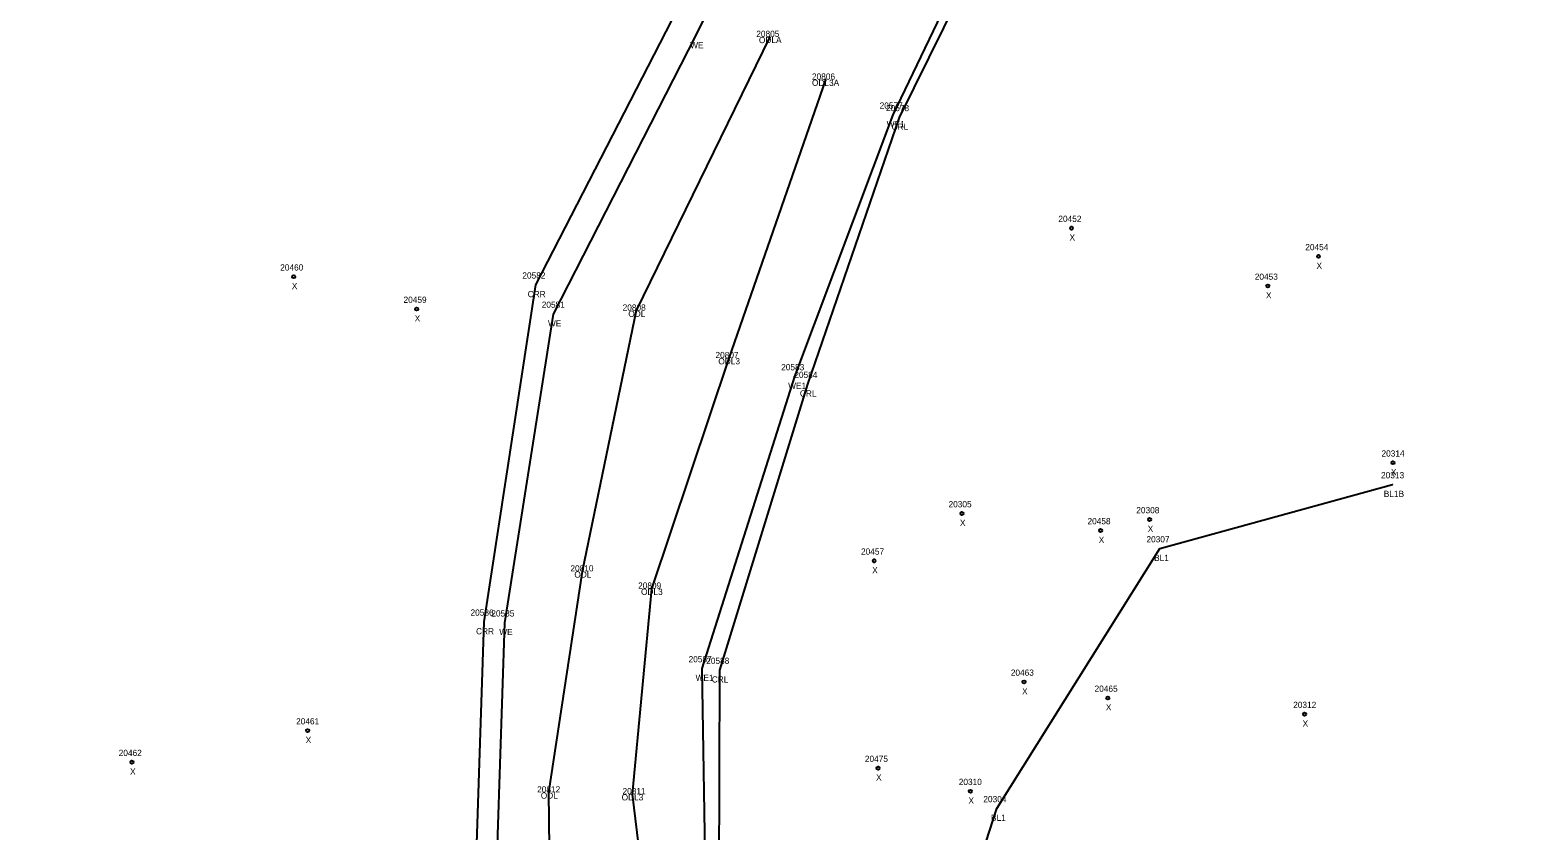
# Model space of a CAD drawing. Extents: x 1965722 to 1969964, y 1117078 to 1118461.
# Drawn here: x 1967718.8 to 1967961.6, y 1117958.8 to 1118087.7 of the extents above; entities that cross this region are included whole.
import ezdxf

# ---------------------------------------------------------------- set-up
doc = ezdxf.new("R2010")
doc.units = 0
for name, color, linetype in [('RD_DTM_BkLn1', 7, 'Continuous'), ('RD_EX_H2O', 7, 'Continuous'), ('RD_EX_H2O_txCode', 7, 'Continuous'), ('RD_SMD_Locator', 7, 'Continuous'), ('RD_SMD_Misc', 7, 'Continuous')]:
    doc.layers.add(name, color=color, linetype=linetype)

msp = doc.modelspace()

# ---------------------------------------------------------------- linework, layer by layer
at = {"layer": 'RD_DTM_BkLn1'}
msp.add_lwpolyline([(1967864.65, 1117932.01), (1967874.44, 1117962.38), (1967900.7, 1118004.22), (1967938.17, 1118014.53)], dxfattribs=at)
at = {"layer": 'RD_EX_H2O'}
for points in [[(1967852.4, 1118390.04), (1967912.21, 1118383.64), (1967925.08, 1118336.82), (1967944.14, 1118294.4), (1967946.67, 1118243.15), (1967961.58, 1118191.28), (1967922.84, 1118148.62), (1967880.18, 1118117.11), (1967858.72, 1118073.64), (1967843.96, 1118030.69), (1967829.77, 1117984.65), (1967829.63, 1117934.73), (1967834.65, 1117903.36)], [(1967848.54, 1118347.45), (1967880.38, 1118337.78), (1967886.93, 1118331.58), (1967896.4, 1118282.85), (1967906.33, 1118232.39), (1967914.38, 1118193.81), (1967904.29, 1118181.59), (1967847.52, 1118139.25), (1967823.99, 1118093.05), (1967800.15, 1118046.69), (1967791.83, 1117992.41), (1967789.93, 1117935.61), (1967798.32, 1117889.19), (1967796.67, 1117880.97)], [(1967849.83, 1118135.18), (1967825.91, 1118086.77), (1967802.99, 1118041.98), (1967795.15, 1117992.28), (1967793.27, 1117935.35), (1967800.64, 1117889.8), (1967800.4, 1117872.52), (1967800.8, 1117854.99), (1967811.67, 1117837.73), (1967837.15, 1117809.04), (1967808.01, 1117752.12), (1967788.48, 1117706.78), (1967783.36, 1117689.17), (1967764.63, 1117648.93), (1967738.42, 1117613.44), (1967731.11, 1117607.31), (1967718.77, 1117573.47), (1967736.01, 1117517.29), (1967781.71, 1117484.69), (1967799.34, 1117478.73), (1967814.43, 1117469.18)], [(1967879.07, 1118118.61), (1967857.7, 1118074.04), (1967841.84, 1118031.93), (1967826.93, 1117984.9), (1967827.73, 1117935.27), (1967832.39, 1117902.59), (1967835.81, 1117893.8), (1967842.37, 1117871.73), (1967853.33, 1117857.05), (1967865.72, 1117824.99), (1967870.38, 1117810.73), (1967864.06, 1117791.33), (1967853.89, 1117756.14), (1967832.83, 1117722.61), (1967813.26, 1117679.41), (1967797.31, 1117630.26), (1967771.82, 1117595.7), (1967769.03, 1117583.97), (1967753.91, 1117565.22), (1967760.74, 1117542.39), (1967793.79, 1117511.28), (1967804.07, 1117502.92), (1967828.12, 1117499.18)], [(1967837.87, 1118086.59), (1967816.35, 1118042.52), (1967807.65, 1118000.54), (1967802.25, 1117964.95), (1967802.7, 1117929.05), (1967808.24, 1117891.66), (1967818.1, 1117847.27), (1967841.92, 1117812.91), (1967830.83, 1117773.47), (1967807.55, 1117730.13), (1967792.1, 1117688.21), (1967759.2, 1117626.42), (1967746.8, 1117597.58), (1967728.31, 1117575.82), (1967748.97, 1117519.79), (1967787.59, 1117491.86), (1967802.7, 1117484.72), (1967813.63, 1117479.24)], [(1967846.86, 1118079.71), (1967831.29, 1118034.88), (1967818.84, 1117997.76), (1967815.72, 1117964.67), (1967820.18, 1117928.06), (1967829.19, 1117896.79), (1967834.11, 1117854.1), (1967863.47, 1117815.02), (1967842.32, 1117765.95), (1967826.02, 1117725.1), (1967807.77, 1117682.35), (1967775.42, 1117611.81), (1967754.74, 1117587.12), (1967745.94, 1117565.65), (1967761.23, 1117525.28), (1967787.1, 1117502.15), (1967805.18, 1117494.11), (1967821.41, 1117490.36)]]:
    msp.add_lwpolyline(points, dxfattribs=at)
at = {"layer": 'RD_SMD_Locator'}
for centre, radius in [((1967825.91, 1118086.77), 0.001), ((1967837.87, 1118086.59), 0.001), ((1967846.86, 1118079.71), 0.001), ((1967857.7, 1118074.04), 0.001), ((1967858.72, 1118073.64), 0.001), ((1967886.47, 1118055.81), 0.25), ((1967926.25, 1118051.25), 0.25), ((1967761.22, 1118047.98), 0.25), ((1967800.15, 1118046.69), 0.001), ((1967918.1, 1118046.49), 0.25), ((1967781.01, 1118042.78), 0.25), ((1967802.99, 1118041.98), 0.001), ((1967816.35, 1118042.52), 0.001), ((1967831.29, 1118034.88), 0.001), ((1967841.84, 1118031.93), 0.001), ((1967843.96, 1118030.69), 0.001), ((1967938.24, 1118018.03), 0.25), ((1967938.17, 1118014.53), 0.001), ((1967868.83, 1118009.86), 0.25), ((1967899.06, 1118008.9), 0.25), ((1967891.17, 1118007.13), 0.25), ((1967900.7, 1118004.22), 0.001), ((1967807.65, 1118000.54), 0.001), ((1967854.7, 1118002.24), 0.25), ((1967818.84, 1117997.76), 0.001), ((1967791.83, 1117992.41), 0.001), ((1967795.15, 1117992.28), 0.001), ((1967826.93, 1117984.9), 0.001), ((1967829.77, 1117984.65), 0.001), ((1967878.84, 1117982.74), 0.25), ((1967892.33, 1117980.16), 0.25), ((1967924.02, 1117977.55), 0.25), ((1967763.46, 1117974.91), 0.25), ((1967735.17, 1117969.82), 0.25), ((1967855.32, 1117968.87), 0.25), ((1967802.25, 1117964.95), 0.001), ((1967815.72, 1117964.67), 0.001), ((1967870.19, 1117965.15), 0.25), ((1967874.44, 1117962.38), 0.001)]:
    msp.add_circle(centre, radius, dxfattribs=at)

# ---------------------------------------------------------------- texts
at = {"layer": 'RD_EX_H2O_txCode'}
for s, p in [('WE', (1967825.07, 1118084.77)), ('20805', (1967835.71, 1118086.59)), ('ODLA', (1967836.14, 1118085.59)), ('20806', (1967844.68, 1118079.71)), ('ODL3A', (1967844.68, 1118078.71)), ('20577', (1967855.58, 1118075.04)), ('20578', (1967856.6, 1118074.64)), ('WE1', (1967856.72, 1118072.04)), ('CRL', (1967857.49, 1118071.64)), ('20582', (1967798.04, 1118047.69)), ('CRR', (1967798.9, 1118044.69)), ('20581', (1967801.16, 1118042.98)), ('20808', (1967814.19, 1118042.52)), ('ODL', (1967815.1, 1118041.52)), ('WE', (1967802.16, 1118039.98)), ('20807', (1967829.14, 1118034.88)), ('ODL3', (1967829.6, 1118033.88)), ('20583', (1967839.72, 1118032.93)), ('20584', (1967841.84, 1118031.69)), ('WE1', (1967840.85, 1118029.93)), ('CRL', (1967842.73, 1118028.69)), ('20810', (1967805.78, 1118000.54)), ('ODL', (1967806.41, 1117999.54)), ('20809', (1967816.68, 1117997.76)), ('ODL3', (1967817.15, 1117996.76)), ('20586', (1967789.69, 1117993.41)), ('20585', (1967793.04, 1117993.28)), ('CRR', (1967790.58, 1117990.41)), ('WE', (1967794.32, 1117990.28)), ('20587', (1967824.81, 1117985.9)), ('20588', (1967827.65, 1117985.65)), ('WE1', (1967825.94, 1117982.9)), ('CRL', (1967828.54, 1117982.65)), ('20812', (1967800.42, 1117964.95)), ('ODL', (1967801.01, 1117963.95)), ('ODL3', (1967814.03, 1117963.67)), ('20811', (1967814.17, 1117964.67))]:
    msp.add_text(s, height=1, dxfattribs=at).set_placement(p)
at = {"layer": 'RD_SMD_Misc'}
for s, p in [('20452', (1967884.36, 1118056.81)), ('X', (1967886.16, 1118053.81)), ('20454', (1967924.13, 1118052.25)), ('20460', (1967759.04, 1118048.98)), ('X', (1967925.93, 1118049.25)), ('X', (1967760.91, 1118045.98)), ('20453', (1967915.99, 1118047.49)), ('20459', (1967778.9, 1118043.78)), ('X', (1967917.79, 1118044.49)), ('X', (1967780.7, 1118040.78)), ('20314', (1967936.4, 1118019.03)), ('20313', (1967936.33, 1118015.53)), ('X', (1967937.92, 1118016.03)), ('BL1B', (1967936.77, 1118012.53)), ('20305', (1967866.67, 1118010.86)), ('20308', (1967896.91, 1118009.9)), ('X', (1967868.51, 1118007.86)), ('20458', (1967889.05, 1118008.13)), ('X', (1967898.75, 1118006.9)), ('X', (1967890.86, 1118005.13)), ('20307', (1967898.55, 1118005.22)), ('20457', (1967852.58, 1118003.24)), ('BL1', (1967899.78, 1118002.22)), ('X', (1967854.38, 1118000.24)), ('20463', (1967876.7, 1117983.74)), ('X', (1967878.52, 1117980.74)), ('20465', (1967890.19, 1117981.16)), ('X', (1967892.01, 1117978.16)), ('20312', (1967922.18, 1117978.55)), ('20461', (1967761.6, 1117975.91)), ('X', (1967923.7, 1117975.55)), ('X', (1967763.14, 1117972.91)), ('20462', (1967733.03, 1117970.82)), ('X', (1967734.86, 1117967.82)), ('20475', (1967853.2, 1117969.87)), ('X', (1967855, 1117966.87)), ('20310', (1967868.32, 1117966.15)), ('X', (1967869.88, 1117963.15)), ('20304', (1967872.28, 1117963.38)), ('BL1', (1967873.51, 1117960.38))]:
    msp.add_text(s, height=1, dxfattribs=at).set_placement(p)

doc.saveas('drawing.dxf')
